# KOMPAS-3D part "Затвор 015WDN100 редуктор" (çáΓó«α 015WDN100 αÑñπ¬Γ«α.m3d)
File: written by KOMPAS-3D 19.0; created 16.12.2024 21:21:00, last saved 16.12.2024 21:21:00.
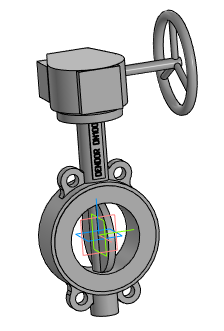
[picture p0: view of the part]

Document properties: Автор: Евгений; Полное имя файла: ..\Затвор 015WDN100 редуктор.a3d

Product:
- Part/product: Затвор 015WDN100 редуктор
    Масса: 13.7776

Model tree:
1. Операция без истории:1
